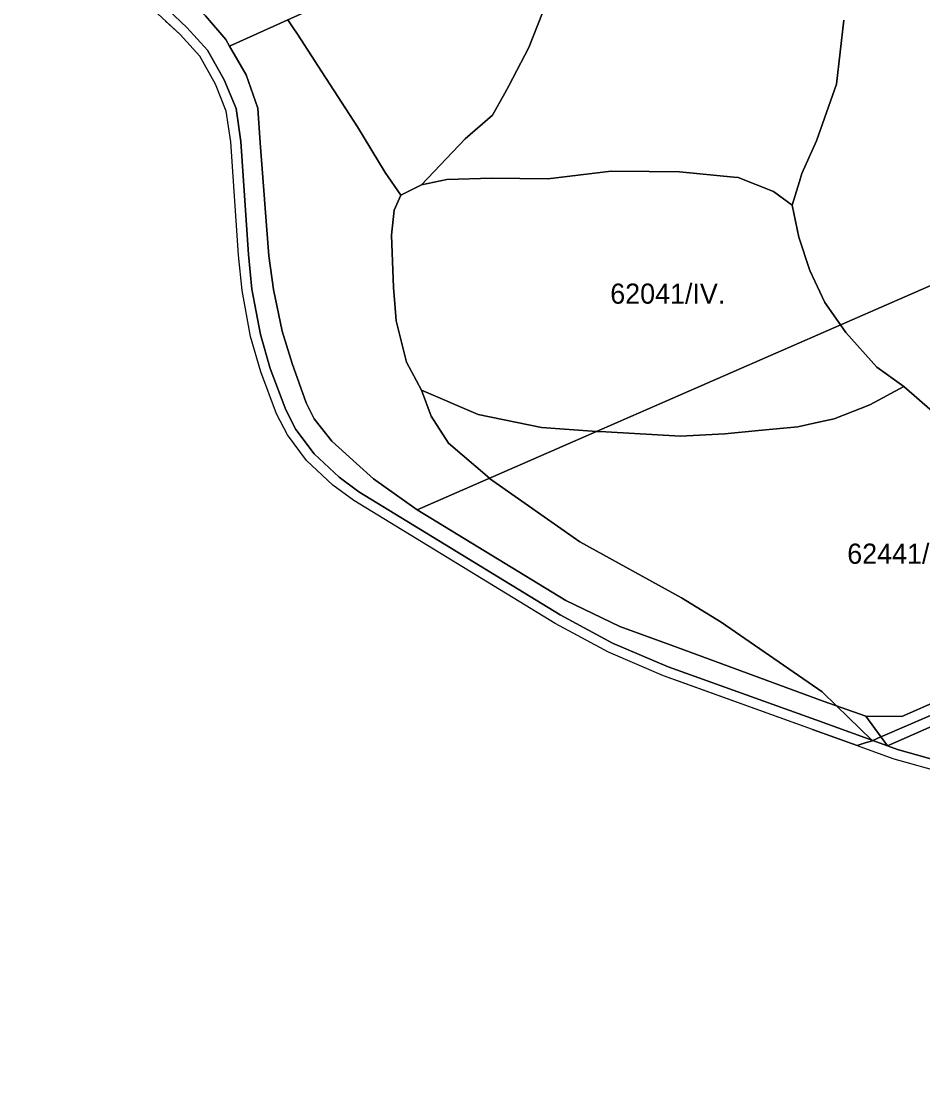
# Model space of a CAD drawing. Extents: x -522079 to -518833, y -1142400 to -1139961.
# Drawn here: x -521476.9 to -521252.6, y -1141773.6 to -1141508 of the extents above; entities that cross this region are included whole.
import ezdxf

# ---------------------------------------------------------------- set-up
doc = ezdxf.new("R2010")
doc.units = 0
for name, color, linetype in [('95560013', 7, 'Continuous'), ('95620013', 7, 'Continuous'), ('95630013', 7, 'Continuous'), ('95640013', 7, 'Continuous'), ('95660013', 7, 'Continuous')]:
    doc.layers.add(name, color=color, linetype=linetype)

msp = doc.modelspace()

# ---------------------------------------------------------------- linework, layer by layer
at = {"layer": '95560013'}
for points in [[(-521431.09, -1141506.63), (-521455.62, -1141481.81), (-521454.54, -1141476.12), (-521272.96, -1141395.84), (-521159.26, -1141346.88), (-521156.76, -1141348.04), (-521153.82, -1141349.39), (-521142.48, -1141389.44), (-521310.56, -1141462.49), (-521425.07, -1141514.17), (-521426.04, -1141512.48)], [(-521378.39, -1141629.5), (-521389.3, -1141621.72), (-521393.54, -1141617.98), (-521399.61, -1141612.42), (-521404.05, -1141606.86), (-521406.05, -1141602.85), (-521409.49, -1141593.05), (-521412.01, -1141585.06), (-521414.13, -1141574.69), (-521415.34, -1141566.3), (-521417.47, -1141538.2), (-521418.07, -1141529.55), (-521421, -1141521.26), (-521425.07, -1141514.17), (-521310.56, -1141462.49), (-521142.48, -1141389.44), (-521107.96, -1141511.35), (-521234.07, -1141566.44)], [(-521257.85, -1141680.84), (-521266.74, -1141680.79), (-521277.4, -1141677.06), (-521313.67, -1141663.71), (-521328.02, -1141658.46), (-521341.44, -1141652.02), (-521378.39, -1141629.5), (-521234.07, -1141566.44), (-521107.96, -1141511.35), (-521083.41, -1141598.05), (-521086.66, -1141604.9), (-521135.66, -1141627.18), (-521182.3, -1141647.66)]]:
    msp.add_lwpolyline(points, close=True, dxfattribs=at)
at = {"layer": '95620013'}
msp.add_lwpolyline([(-521261.42, -1141688.16), (-521185.06, -1141654.56), (-521146.44, -1141773.64), (-521153.73, -1141764.26), (-521160.88, -1141756.78), (-521181.74, -1141737.31), (-521186.22, -1141732.52), (-521191.06, -1141726.58), (-521193.87, -1141721.1), (-521196.27, -1141715.36), (-521198.1, -1141710.58), (-521201.07, -1141705.38), (-521205.36, -1141700.71), (-521210.58, -1141697.9), (-521216.85, -1141696.44), (-521234.23, -1141694.42), (-521246.75, -1141692.49), (-521258.87, -1141689.08)], close=True, dxfattribs=at)
at = {"layer": '95630013'}
for points in [[(-521474.82, -1141472.48), (-521435.7, -1141509.5), (-521430.56, -1141515.15), (-521426.4, -1141522.52), (-521423.45, -1141529.64), (-521422.3, -1141537.87), (-521420.36, -1141565.98), (-521419.55, -1141574.63), (-521417.39, -1141585.84), (-521415, -1141594.31), (-521411.13, -1141604.62), (-521408.6, -1141609.5), (-521404.06, -1141615.52), (-521397.79, -1141621.36), (-521392.9, -1141624.99), (-521342.84, -1141655.56), (-521329.77, -1141662.64), (-521315.94, -1141668.52), (-521279.18, -1141681.72), (-521261.42, -1141688.16), (-521258.87, -1141689.08), (-521246.75, -1141692.49)], [(-521247.24, -1141694.95), (-521259.69, -1141691.44), (-521280.03, -1141684.05), (-521317.08, -1141670.75), (-521330.81, -1141664.89), (-521344.1, -1141657.73), (-521394.19, -1141627.12), (-521399.42, -1141623.32), (-521405.95, -1141617.2), (-521410.67, -1141610.84), (-521413.41, -1141605.57), (-521417.34, -1141595.15), (-521419.85, -1141586.36), (-521421.99, -1141574.92), (-521422.84, -1141566.15), (-521424.81, -1141537.99), (-521425.94, -1141530.31), (-521428.59, -1141523.58), (-521432.52, -1141516.64), (-521437.41, -1141511.31), (-521476.9, -1141474.65)]]:
    msp.add_lwpolyline(points, dxfattribs=at)
at = {"layer": '95640013'}
msp.add_lwpolyline([(-521431.09, -1141506.63), (-521426.04, -1141512.48), (-521425.07, -1141514.17), (-521421, -1141521.26), (-521418.07, -1141529.55), (-521417.47, -1141538.2), (-521415.34, -1141566.3), (-521414.13, -1141574.69), (-521412.01, -1141585.06), (-521409.49, -1141593.05), (-521406.05, -1141602.85), (-521404.05, -1141606.86), (-521399.61, -1141612.42), (-521393.54, -1141617.98), (-521389.3, -1141621.72), (-521378.39, -1141629.5), (-521341.44, -1141652.02), (-521328.02, -1141658.46), (-521313.67, -1141663.71), (-521277.4, -1141677.06), (-521266.74, -1141680.79), (-521261.42, -1141688.16), (-521279.18, -1141681.72), (-521315.94, -1141668.52), (-521329.77, -1141662.64), (-521342.84, -1141655.56), (-521392.9, -1141624.99), (-521397.79, -1141621.36), (-521404.06, -1141615.52), (-521408.6, -1141609.5), (-521411.13, -1141604.62), (-521415, -1141594.31), (-521417.39, -1141585.84), (-521419.55, -1141574.63), (-521420.36, -1141565.98), (-521422.3, -1141537.87), (-521423.45, -1141529.64), (-521426.4, -1141522.52), (-521430.56, -1141515.15), (-521435.7, -1141509.5), (-521474.82, -1141472.48)], dxfattribs=at)
msp.add_lwpolyline([(-521257.85, -1141680.84), (-521182.3, -1141647.66), (-521180.65, -1141652.62), (-521185.06, -1141654.56), (-521261.42, -1141688.16), (-521266.74, -1141680.79)], close=True, dxfattribs=at)
at = {"layer": '95660013'}
for points in [[(-521346.12, -1141503.16), (-521350.65, -1141514.51), (-521355.64, -1141524.06), (-521356.63, -1141525.82), (-521359.71, -1141531.33), (-521366.51, -1141537.24), (-521377.32, -1141548.65), (-521382.51, -1141551.25), (-521386.41, -1141545.61), (-521393.27, -1141534.25), (-521402.15, -1141520.52), (-521408.17, -1141511.22), (-521409.25, -1141509.65), (-521410.62, -1141507.65)], [(-521272.28, -1141507.7), (-521274.09, -1141523.6), (-521279.08, -1141537.69), (-521282.7, -1141545.87), (-521283.29, -1141547.81), (-521285.08, -1141553.69), (-521289.78, -1141550.27), (-521298.53, -1141546.86), (-521299.66, -1141546.75), (-521313.12, -1141545.4), (-521320.68, -1141545.32), (-521330.15, -1141545.23), (-521345.87, -1141547.18), (-521359.81, -1141547.02), (-521371, -1141547.35), (-521377.32, -1141548.65), (-521366.51, -1141537.24), (-521359.71, -1141531.33), (-521356.63, -1141525.82), (-521355.64, -1141524.06), (-521350.65, -1141514.51), (-521346.12, -1141503.16)], [(-521410.62, -1141507.65), (-521409.25, -1141509.65), (-521408.17, -1141511.22), (-521402.15, -1141520.52), (-521393.27, -1141534.25), (-521386.41, -1141545.61), (-521382.51, -1141551.25), (-521384.13, -1141554.99), (-521384.78, -1141561.17), (-521384.29, -1141574.18), (-521383.98, -1141578.21), (-521383.65, -1141582.48), (-521381.05, -1141592.72), (-521377.32, -1141599.7), (-521374.94, -1141606.2), (-521370.61, -1141612.93), (-521360.45, -1141621.6), (-521360.4, -1141621.64), (-521337.97, -1141637.43), (-521312.68, -1141651.31), (-521302.74, -1141657.38), (-521277.67, -1141674.73), (-521274.06, -1141678.23), (-521271.16, -1141681.04), (-521265.26, -1141686.76), (-521265.17, -1141686.85), (-521265.13, -1141686.9), (-521266.91, -1141687.44), (-521268.94, -1141688.07), (-521280.03, -1141684.05), (-521313.43, -1141672.06), (-521317.08, -1141670.75), (-521330.81, -1141664.89), (-521344.1, -1141657.73), (-521394.19, -1141627.12), (-521399.42, -1141623.32), (-521405.95, -1141617.2), (-521410.67, -1141610.84), (-521413.41, -1141605.57), (-521417.34, -1141595.15), (-521419.85, -1141586.36), (-521421.99, -1141574.92), (-521422.84, -1141566.15), (-521424.81, -1141537.99), (-521425.94, -1141530.31), (-521428.59, -1141523.58), (-521432.52, -1141516.64), (-521437.41, -1141511.31), (-521441.06, -1141507.92)], [(-521239.84, -1141614.01), (-521257.35, -1141598.83), (-521264, -1141594.02), (-521271.78, -1141585.4), (-521273.1, -1141583.5), (-521276.97, -1141577.92), (-521280.7, -1141569.95), (-521283.46, -1141561.66), (-521285.08, -1141553.69), (-521283.29, -1141547.81), (-521282.7, -1141545.87), (-521279.08, -1141537.69), (-521274.09, -1141523.6), (-521272.28, -1141507.7)], [(-521204.3, -1141660.61), (-521262.08, -1141685.51), (-521263.02, -1141685.94), (-521265.03, -1141686.85), (-521265.13, -1141686.9), (-521265.17, -1141686.85), (-521265.26, -1141686.76), (-521271.16, -1141681.04), (-521274.06, -1141678.23), (-521277.67, -1141674.73), (-521302.74, -1141657.38), (-521312.68, -1141651.31), (-521337.97, -1141637.43), (-521360.4, -1141621.64), (-521360.45, -1141621.6), (-521370.61, -1141612.93), (-521374.94, -1141606.2), (-521377.32, -1141599.7), (-521363.26, -1141605.77), (-521347.49, -1141609.02), (-521333.68, -1141609.96), (-521331.49, -1141610.11), (-521312.9, -1141611.19), (-521301.88, -1141610.54), (-521293.45, -1141609.74), (-521283.72, -1141608.81), (-521279.31, -1141607.86), (-521274.64, -1141606.85), (-521265.78, -1141603.38), (-521257.35, -1141598.83), (-521239.84, -1141614.01)], [(-521247.24, -1141694.95), (-521259.69, -1141691.44), (-521280.03, -1141684.05), (-521268.94, -1141688.07), (-521266.91, -1141687.44), (-521265.13, -1141686.9), (-521265.03, -1141686.85), (-521263.02, -1141685.94), (-521262.08, -1141685.51), (-521204.3, -1141660.61)]]:
    msp.add_lwpolyline(points, dxfattribs=at)
msp.add_lwpolyline([(-521298.53, -1141546.86), (-521289.78, -1141550.27), (-521285.08, -1141553.69), (-521283.46, -1141561.66), (-521280.7, -1141569.95), (-521276.97, -1141577.92), (-521273.1, -1141583.5), (-521271.78, -1141585.4), (-521264, -1141594.02), (-521257.35, -1141598.83), (-521265.78, -1141603.38), (-521274.64, -1141606.85), (-521279.31, -1141607.86), (-521283.72, -1141608.81), (-521293.45, -1141609.74), (-521301.88, -1141610.54), (-521312.9, -1141611.19), (-521331.49, -1141610.11), (-521333.68, -1141609.96), (-521347.49, -1141609.02), (-521363.26, -1141605.77), (-521377.32, -1141599.7), (-521381.05, -1141592.72), (-521383.65, -1141582.48), (-521383.98, -1141578.21), (-521384.29, -1141574.18), (-521384.78, -1141561.17), (-521384.13, -1141554.99), (-521382.51, -1141551.25), (-521377.32, -1141548.65), (-521371, -1141547.35), (-521359.81, -1141547.02), (-521345.87, -1141547.18), (-521330.15, -1141545.23), (-521320.68, -1141545.32), (-521313.12, -1141545.4), (-521299.66, -1141546.75)], close=True, dxfattribs=at)

# ---------------------------------------------------------------- texts
for s, rotation, p in [('62041/IV.', 360, (-521330.37, -1141578.21)), ('62441/III.', 0, (-521271.4, -1141642.87))]:
    msp.add_text(s, height=5, rotation=rotation, dxfattribs=at).set_placement(p)

doc.saveas('drawing.dxf')
